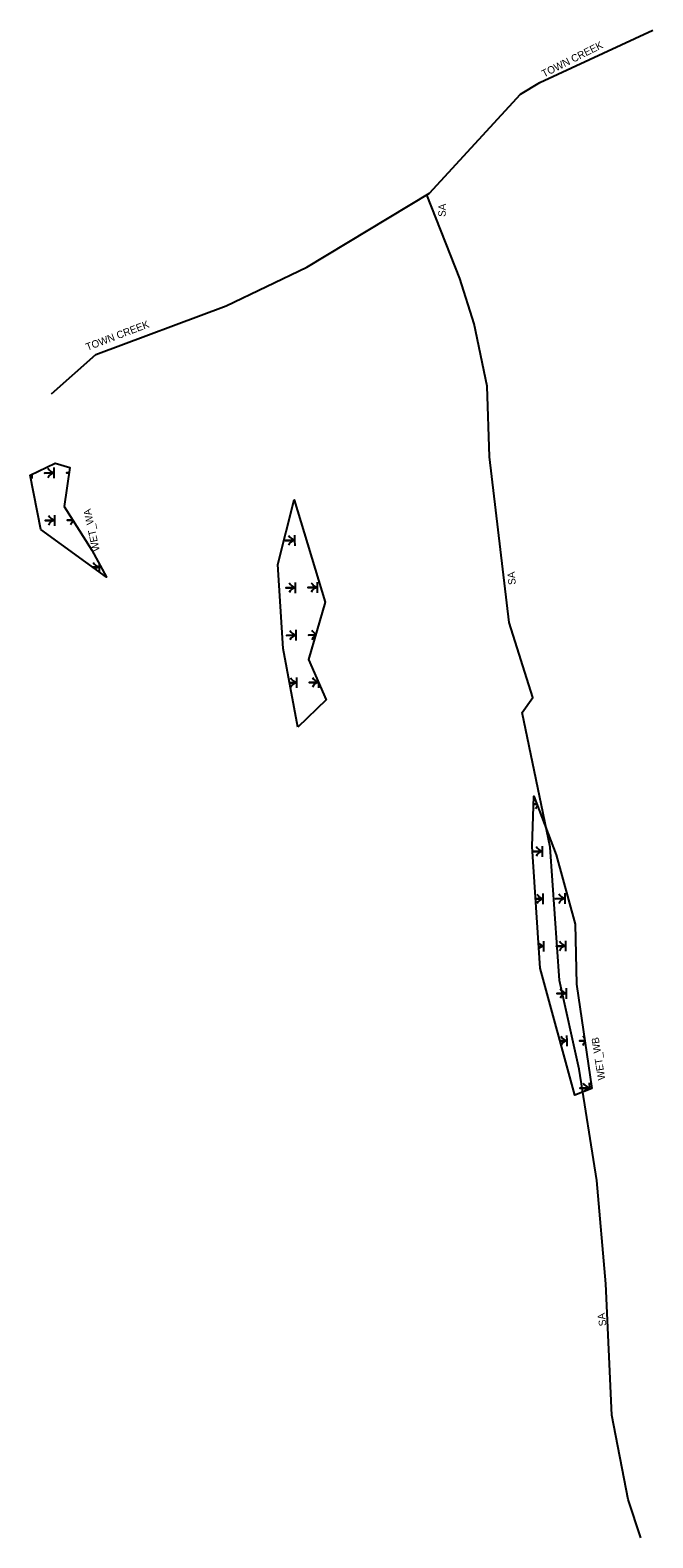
# Model space of a CAD drawing. Extents: x 1503676 to 1665494, y 654328 to 989038.
# Drawn here: x 1555945 to 1556198, y 692718 to 693331 of the extents above; entities that cross this region are included whole.
import ezdxf

# ---------------------------------------------------------------- set-up
doc = ezdxf.new("R2010")
doc.units = 0
for name, color, linetype in [('Level 16', 7, 'Continuous'), ('Level 26', 7, 'Continuous'), ('Level 3', 7, 'Continuous')]:
    doc.layers.add(name, color=color, linetype=linetype)

msp = doc.modelspace()

# ---------------------------------------------------------------- linework, layer by layer
at = {"layer": 'Level 16'}
for points in [[(1555953.58, 693183.27), (1555971.69, 693199.23), (1556024.64, 693219.02), (1556057.5, 693234.81), (1556107.38, 693264.83), (1556144.41, 693305.15), (1556152.26, 693309.94), (1556198.29, 693331.22)], [(1556193.44, 692717.79), (1556188.23, 692733.34), (1556181.56, 692767.76), (1556179.21, 692821.16), (1556175.51, 692863.12), (1556168.3, 692908.53), (1556160.3, 692944.53), (1556156.57, 692998.86), (1556145.11, 693053.57), (1556149.51, 693059.69), (1556139.83, 693090.23), (1556131.88, 693157.57), (1556130.92, 693186.33), (1556125.59, 693211.67), (1556119.81, 693230.21), (1556106.34, 693264.2)]]:
    msp.add_lwpolyline(points, dxfattribs=at)
at = {"layer": 'Level 3'}
for p, q in [((1555945.83, 693148.79), (1555945.81, 693150.58)), ((1556062.41, 693063.69), (1556062.39, 693065.52)), ((1556151.11, 693016.33), (1556149.8, 693016.31)), ((1556149.8, 693016.31), (1556151.11, 693016.33))]:
    msp.add_line(p, q, dxfattribs=at)
for points in [[(1555970.08, 693119.71), (1555976.02, 693108.64), (1555949.31, 693128.05), (1555944.95, 693150.16), (1555955.1, 693155.04), (1555961.09, 693153.22), (1555958.75, 693137.38)], [(1556053.9, 693047.64), (1556047.95, 693079.64), (1556045.67, 693113.83), (1556052.4, 693140.15), (1556064.92, 693098.47), (1556058.14, 693075.13), (1556065.39, 693058.71)], [(1556173.49, 692900.64), (1556166.54, 692897.94), (1556152.41, 692949.52), (1556149.22, 692999.07), (1556149.9, 693019.55), (1556158.9, 692995.63), (1556166.71, 692967.48), (1556167.25, 692943.08)]]:
    msp.add_lwpolyline(points, close=True, dxfattribs=at)
for points in [[(1555954.77, 693148.91), (1555954.75, 693151.06), (1555950.8, 693151.01), (1555954.75, 693151.06), (1555954.72, 693153.21)], [(1555960.78, 693151.14), (1555959.74, 693151.13), (1555960.78, 693151.14)], [(1555955.03, 693129.61), (1555955, 693131.76), (1555951.05, 693131.71), (1555955, 693131.76), (1555954.97, 693133.91)], [(1555962.29, 693131.86), (1555960, 693131.83), (1555962.29, 693131.86)], [(1556052.71, 693121.47), (1556052.68, 693123.62), (1556048.74, 693123.57), (1556052.68, 693123.62), (1556052.65, 693125.77)], [(1555970.49, 693112.66), (1555973.14, 693112.7), (1555973.12, 693114.04)], [(1555973.17, 693110.71), (1555973.14, 693112.7), (1555970.49, 693112.66)], [(1556052.96, 693102.17), (1556052.93, 693104.32), (1556048.99, 693104.27), (1556052.93, 693104.32), (1556052.91, 693106.47)], [(1556061.91, 693102.29), (1556061.88, 693104.44), (1556057.93, 693104.39), (1556061.88, 693104.44), (1556061.85, 693106.59)], [(1556053.22, 693082.87), (1556053.19, 693085.02), (1556049.24, 693084.97), (1556053.19, 693085.02), (1556053.16, 693087.17)], [(1556061.05, 693085.13), (1556058.19, 693085.09), (1556061.05, 693085.13)], [(1556050.54, 693065.69), (1556053.44, 693065.72), (1556053.41, 693067.87)], [(1556053.47, 693063.57), (1556053.44, 693065.72), (1556050.54, 693065.69)], [(1556062.25, 693065.84), (1556058.44, 693065.79), (1556062.25, 693065.84)], [(1556153.46, 692994.91), (1556153.43, 692997.06), (1556149.49, 692997.01), (1556153.43, 692997.06), (1556153.41, 692999.21)], [(1556150.6, 692977.72), (1556153.69, 692977.76), (1556153.66, 692979.91)], [(1556153.72, 692975.61), (1556153.69, 692977.76), (1556150.6, 692977.72)], [(1556162.66, 692975.73), (1556162.63, 692977.88), (1556158.69, 692977.82), (1556162.63, 692977.88), (1556162.6, 692980.03)], [(1556151.84, 692958.43), (1556153.94, 692958.46), (1556153.91, 692960.61)], [(1556153.97, 692956.31), (1556153.94, 692958.46), (1556151.84, 692958.43)], [(1556162.91, 692956.43), (1556162.88, 692958.58), (1556158.94, 692958.53), (1556162.88, 692958.58), (1556162.86, 692960.73)], [(1556163.17, 692937.13), (1556163.14, 692939.28), (1556159.19, 692939.23), (1556163.14, 692939.28), (1556163.11, 692941.43)], [(1556160.51, 692919.94), (1556163.39, 692919.98), (1556163.36, 692922.13)], [(1556163.42, 692917.83), (1556163.39, 692919.98), (1556160.51, 692919.94)], [(1556170.63, 692920.07), (1556168.39, 692920.04), (1556170.63, 692920.07)], [(1556172.6, 692900.29), (1556172.59, 692900.8), (1556168.64, 692900.75), (1556172.59, 692900.8), (1556172.56, 692902.95)]]:
    msp.add_lwpolyline(points, dxfattribs=at)
for centre, radius, start, end in [((1555956.2, 693155.64), 4.81, 212.87874, 252.37348), ((1555955.01, 693148), 3.07, 94.89164, 158.28626), ((1555955.26, 693128.7), 3.07, 94.89164, 158.28626), ((1555956.45, 693136.34), 4.81, 212.87874, 252.37348), ((1555964.21, 693128.81), 3.07, 122.06491, 158.28626), ((1556052.94, 693120.56), 3.07, 94.89164, 158.28626), ((1556054.14, 693128.2), 4.81, 212.87874, 252.37348), ((1555974.6, 693117.28), 4.81, 212.87874, 252.37348), ((1555973.4, 693109.63), 3.07, 94.89164, 130.15388), ((1556053.2, 693101.26), 3.07, 94.89164, 158.28626), ((1556054.39, 693108.9), 4.81, 212.87874, 252.37348), ((1556062.14, 693101.38), 3.07, 94.89164, 158.28626), ((1556063.33, 693109.02), 4.81, 212.87874, 252.37348), ((1556054.64, 693089.6), 4.81, 212.87874, 252.37348), ((1556063.59, 693089.72), 4.81, 212.87874, 239.85262), ((1556053.45, 693081.96), 3.07, 94.89164, 158.28626), ((1556062.39, 693082.08), 3.07, 118.03873, 158.28626), ((1556054.9, 693070.3), 4.81, 212.87874, 252.37348), ((1556063.84, 693070.42), 4.81, 212.87874, 250.31133), ((1556053.7, 693062.66), 3.07, 94.89164, 156.72393), ((1556062.65, 693062.78), 3.07, 97.38705, 158.28626), ((1556153.44, 693013.29), 3.07, 131.81303, 158.28626), ((1556153.7, 692994), 3.07, 94.89164, 158.28626), ((1556154.89, 693001.64), 4.81, 212.87874, 252.37348), ((1556153.95, 692974.7), 3.07, 94.89164, 158.28626), ((1556155.14, 692982.34), 4.81, 212.87874, 252.37348), ((1556162.89, 692974.81), 3.07, 94.89164, 158.28626), ((1556164.09, 692982.46), 4.81, 212.87874, 252.37348), ((1556155.4, 692963.04), 4.81, 220.51483, 252.37348), ((1556154.2, 692955.4), 3.07, 94.89164, 138.44373), ((1556163.15, 692955.51), 3.07, 94.89164, 158.28626), ((1556164.34, 692963.16), 4.81, 212.87874, 252.37348), ((1556163.4, 692936.21), 3.07, 94.89164, 158.28626), ((1556164.59, 692943.86), 4.81, 212.87874, 252.37348), ((1556164.85, 692924.56), 4.81, 212.87874, 252.37348), ((1556163.65, 692916.92), 3.07, 94.89164, 151.7643), ((1556173.79, 692924.68), 4.81, 212.87874, 226.2191), ((1556172.6, 692917.03), 3.07, 127.61523, 158.28626), ((1556174.04, 692905.38), 4.81, 212.87874, 252.37348), ((1556172.85, 692897.73), 3.07, 94.89164, 147.54577)]:
    msp.add_arc(centre, radius, start, end, dxfattribs=at)

# ---------------------------------------------------------------- texts
at = {"layer": 'Level 26'}
for s, rotation, p in [('TOWN CREEK', 26.73202, (1556154, 693311.94)), ('SA', 88.92959, (1556113.98, 693255.24)), ('TOWN CREEK', 20.77083, (1555968.26, 693200.75)), ('WET_WA', 102.37237, (1555973.29, 693119.49)), ('SA', 95.73373, (1556142.56, 693105.69)), ('WET_WB', 98.82486, (1556178.94, 692904.26)), ('SA', 98.57671, (1556179.45, 692804.15))]:
    msp.add_text(s, height=3, rotation=rotation, dxfattribs=at).set_placement(p)

doc.saveas('drawing.dxf')
